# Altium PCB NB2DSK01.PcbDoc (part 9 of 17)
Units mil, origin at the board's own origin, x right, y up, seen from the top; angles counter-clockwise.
Board outline 11815 x 6500.03 mil, 8 copper layers (Top Layer, MidLayer1, MidLayer2, GND, PWR, MidLayer3, MidLayer4, Bottom Layer), stack 74.62 mil thick; 798 components, 1002 nets, 3927 pads, 3182 vias.
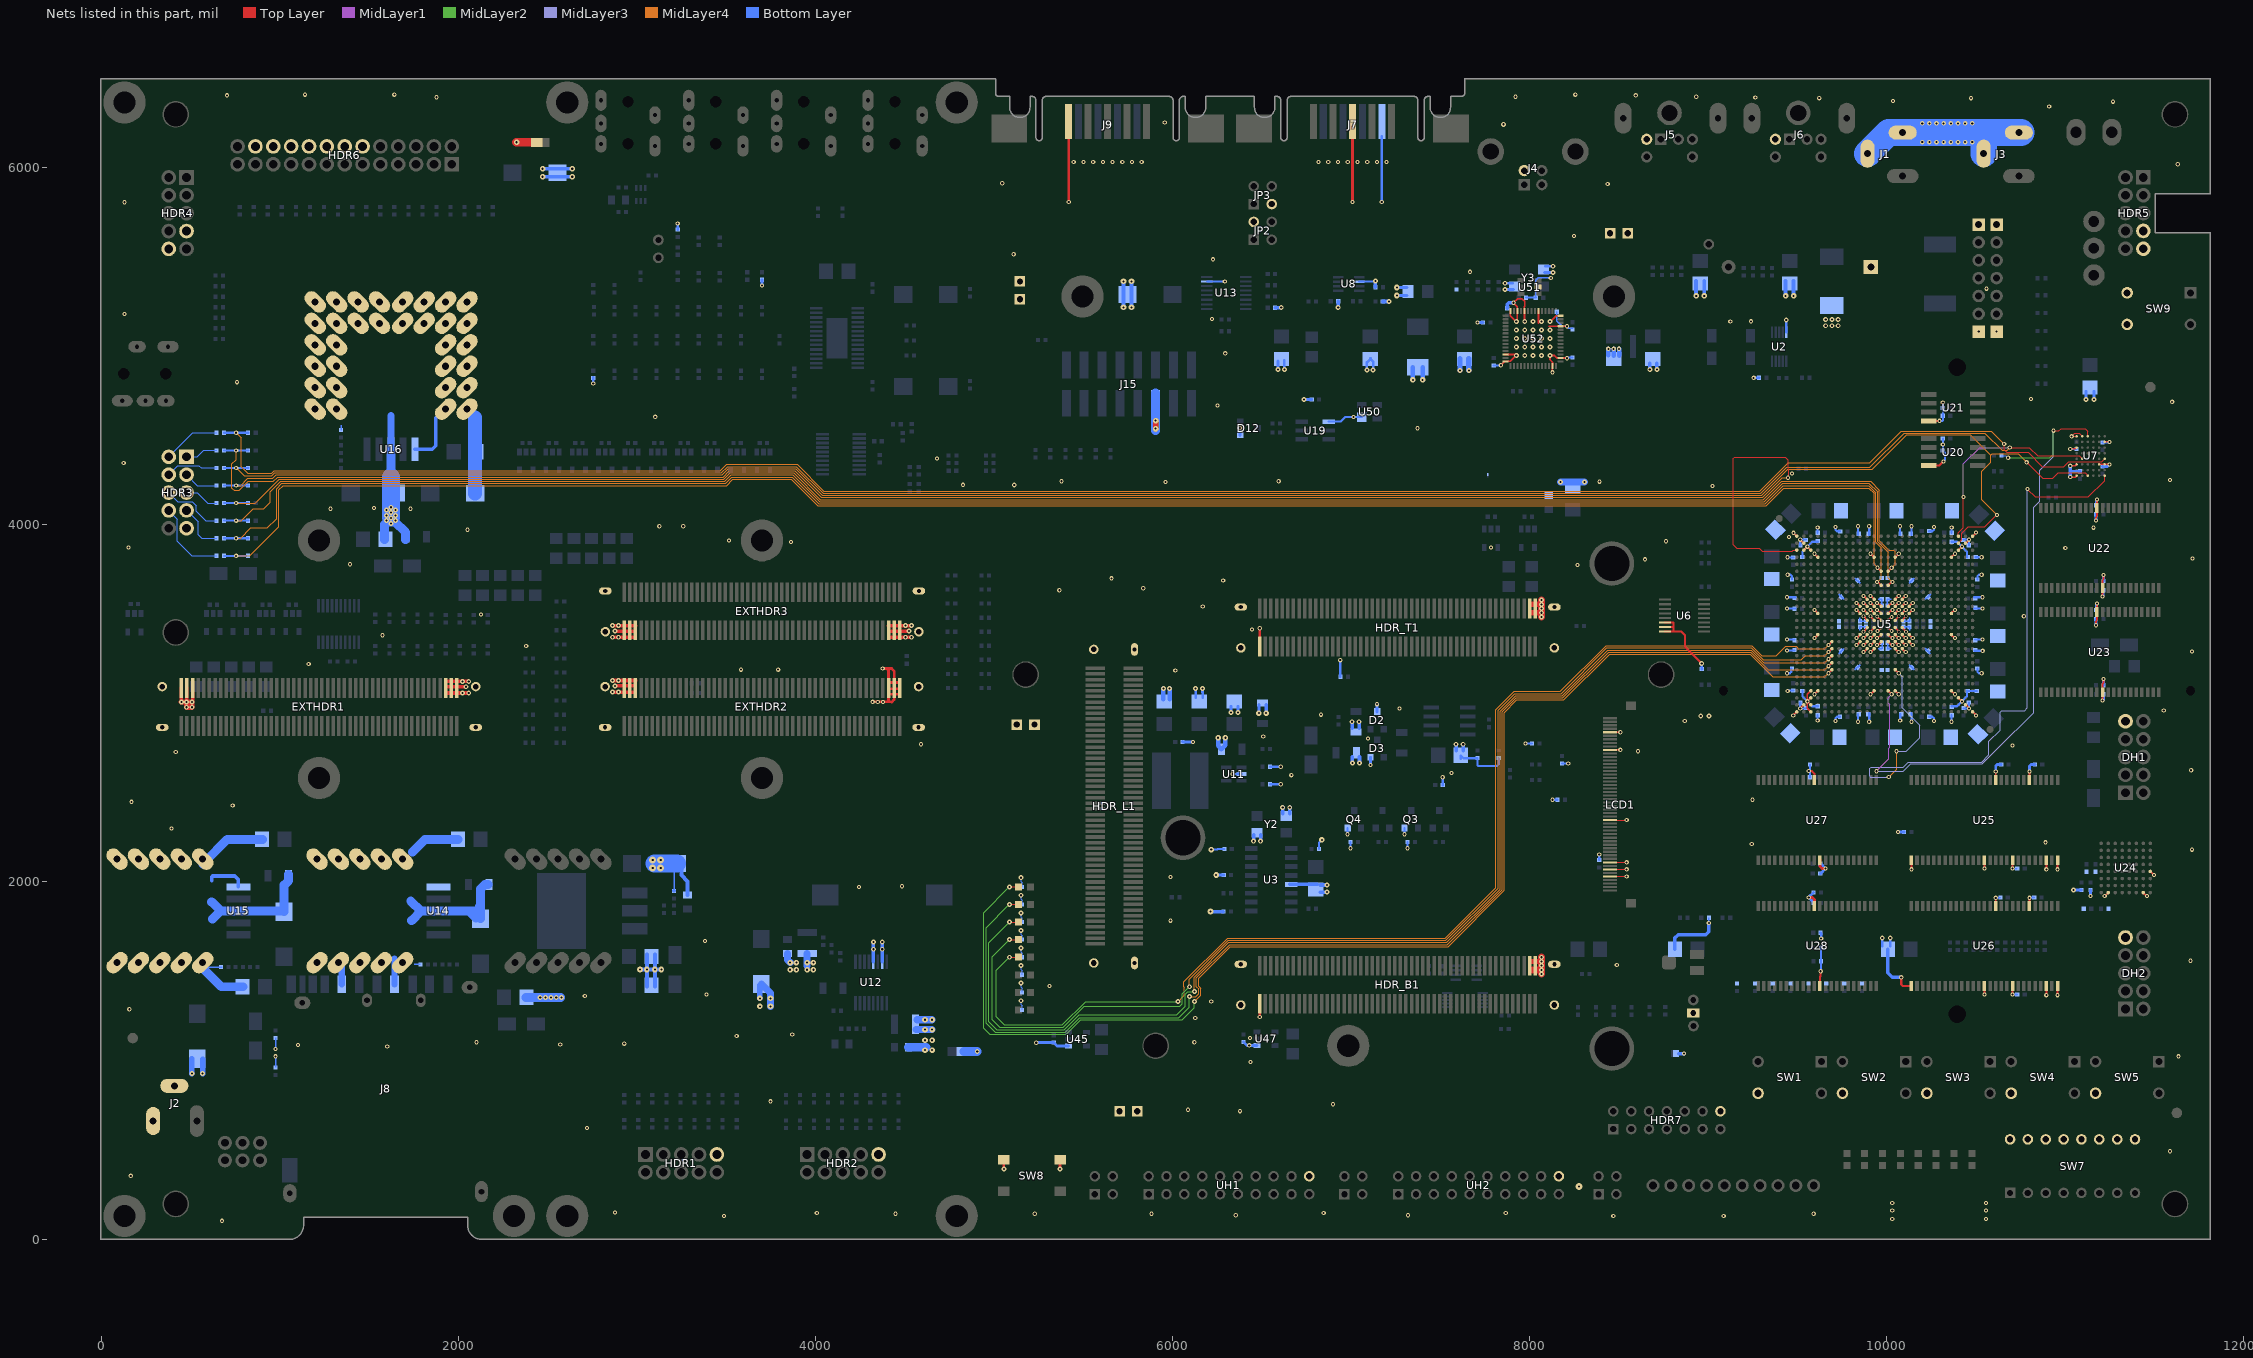
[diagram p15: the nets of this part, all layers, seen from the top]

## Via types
v1: diameter 23.62, hole 11.81, Top Layer to Bottom Layer, tented both sides, 1950 vias
v2: diameter 27.56, hole 11.81, Top Layer to Bottom Layer, tented both sides, 679 vias
v3: diameter 23.62, hole 11.81, Top Layer to Bottom Layer, 194 vias
v4: diameter 31.5, hole 11.81, Top Layer to Bottom Layer, tented both sides, 178 vias
v5: diameter 21.65, hole 11.81, Top Layer to Bottom Layer, tented both sides, 67 vias
v6: diameter 23.62, hole 11.81, Top Layer to Bottom Layer, tented bottom, 53 vias
v7: diameter 26, hole 11.81, Top Layer to Bottom Layer, tented both sides, 21 vias
v8: diameter 26, hole 11.81, Top Layer to Bottom Layer, 13 vias
v9: diameter 28, hole 11.81, Top Layer to Bottom Layer, 8 vias
v10: diameter 25.59, hole 11.81, Top Layer to Bottom Layer, tented both sides, 7 vias
v11: diameter 39.37, hole 11.81, Top Layer to Bottom Layer, tented both sides, 5 vias
v12: diameter 30, hole 11.81, Top Layer to Bottom Layer, 3 vias
v13: diameter 30, hole 11.81, Top Layer to Bottom Layer, tented both sides, 2 vias
v14: diameter 23, hole 11.81, Top Layer to Bottom Layer, tented both sides, 1 vias
v15: diameter 26.56, hole 11.81, Top Layer to Bottom Layer, tented both sides, 1 vias

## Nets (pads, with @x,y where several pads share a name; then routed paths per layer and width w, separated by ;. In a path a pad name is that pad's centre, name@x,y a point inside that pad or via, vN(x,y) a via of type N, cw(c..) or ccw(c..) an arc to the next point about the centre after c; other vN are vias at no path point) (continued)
GND: BT1.2 C1.2 C2.2 C3.2 C4.2 C10.2 C11.2 C12.2 C13.2 C14.2 C15.2 C18.2 C19.2 C20.2 C21.2 C22.2 C23.2 C24.2 C25.2 C26.2 C27.2 C28.2 C29.2 C30.2 C31.2 C32.2 C33.2 C34.2 C35.2 C36.2 C37.2 C38.2 C39.2 C40.2 C41.2 C42.2 C43.2 C44.2 C45.2 C46.2 C47.2 C48.2 C49.2 C50.2 C51.2 C52.2 C53.2 C54.2 C55.2 C56.2 C57.2 C58.2 C59.2 C60.2 C61.2 C62.2 C63.2 C64.2 C65.2 C66.2 C67.2 C68.2 C69.2 C70.2 C71.2 C72.2 C73.2 C74.2 C75.2 C76.2 C77.2 C78.2 C79.2 C80.2 C81.2 C82.2 C83.2 C84.2 C85.2 C86.2 C87.2 C88.2 C89.2 C90.2 C91.2 C92.2 C93.2 C94.2 C95.2 C96.2 C97.2 C98.2 C99.2 C100.2 C101.2 C102.2 C103.2 C104.2 C105.2 C106.2 C107.2 C108.2 C109.2 C110.2 C111.2 C112.2 C113.2 C114.2 C115.2 C116.2 C117.2 C118.2 C119.1 C120.2 C121.2 C122.2 C123.2 C124.2 C125.2 C126.2 C127.2 C128.2 C129.1 C130.2 C132.2 C133.2 C134.2 C135.2 C136.2 C137.2 C138.1 C139.1 C140.2 C141.2 C142.1 C143.2 C144.1 C146.1 C147.1 C148.1 C149.1 C150.2 C156.2 C157.2 C158.2 C159.2 C160.2 C161.2 C162.2 C163.2 C164.2 C165.2 C166.2 C167.2 C168.2 C169.2 C170.2 C172.2 C181.2 C189.2 C199.2 C200.1 C201.2 C202.1 C203.2 C204.2 C205.2 C206.2 C207.2 C208.2 C209.2 C210.2 C211.2 C212.2 C213.2 C214.2 C215.2 C216.2 C217.2 C218.2 C219.2 C220.2 C221.2 C222.2 C223.2 C224.2 C225.2 C226.2 C227.2 C228.2 C229.2 C230.2 C231.2 C232.2 C233.2 C234.2 C251.2 C253.2 C263.1 C264.1 C265.1 C266.2 C267.2 C268.2 C269.2 C270.2 C271.2 C272.1 C273.2 D1.1 D2.2 D3.2 D12.1 DH1.9 DH2.9 EXTHDR1.1 EXTHDR1.3 EXTHDR1.5 EXTHDR1.95 EXTHDR1.97 EXTHDR1.99 EXTHDR1.MH1 EXTHDR1.MH2 EXTHDR1.MH3 EXTHDR1.MH4 EXTHDR2.1 EXTHDR2.3 EXTHDR2.5 EXTHDR2.95 EXTHDR2.97 EXTHDR2.99 EXTHDR2.MH1 EXTHDR2.MH2 EXTHDR2.MH3 EXTHDR2.MH4 EXTHDR3.1 EXTHDR3.3 EXTHDR3.5 EXTHDR3.95 EXTHDR3.97 EXTHDR3.99 EXTHDR3.MH1 EXTHDR3.MH2 EXTHDR3.MH3 EXTHDR3.MH4 GP1.1 GP1.2 GP2.1 GP2.2 GP3.1 GP3.2 GP4.1 GP4.2 HDR1.9 HDR2.9 HDR3.9 HDR4.7 HDR4.10 HDR5.7 HDR5.9 HDR6.19 HDR6.20 HDR6.21 HDR6.22 HDR6.23 HDR6.24 HDR6.25 HDR7.14 HDR_B1.1 HDR_B1.98 HDR_B1.100 HDR_B1.MH1 HDR_B1.MH2 HDR_B1.MH3 HDR_B1.MH4 HDR_L1.MH1 HDR_L1.MH2 HDR_L1.MH3 HDR_L1.MH4 HDR_T1.1 HDR_T1.98 HDR_T1.100 HDR_T1.MH1 HDR_T1.MH2 HDR_T1.MH3 HDR_T1.MH4 J1.2 J1.3 J2.2 J2.3 J3.2 J3.3 J4.4 J5.3 J6.3 J7.3 J7.6 J8.3 J8.6 J9.5 J15.5 JP2.2 JP3.3 LCD1.5 LCD1.7 LCD1.9 LCD1.21 LCD1.41 LCD1.46 NT1.2 NT2.1 NT4.2 NT6.1 pad.0@88.68,1548.45 pad.0@88.68,2128.45 pad.0@208.68,1548.45 pad.0@208.68,2128.45 pad.0@328.68,1548.45 pad.0@328.68,2128.45 pad.0@448.68,1548.45 pad.0@448.68,2128.45 pad.0@568.68,1548.45 pad.0@568.68,2128.45 pad.0@1198.68,4648.45 pad.0@1198.68,4768.45 pad.0@1198.68,4888.45 pad.0@1198.68,5008.45 pad.0@1198.68,5128.45 pad.0@1198.68,5248.45 pad.0@1208.68,1548.45 pad.0@1208.68,2128.45 pad.0@1318.68,4648.45 pad.0@1318.68,4768.45 pad.0@1318.68,4888.45 pad.0@1318.68,5008.45 pad.0@1318.68,5128.45 pad.0@1318.68,5248.45 pad.0@1328.68,1548.45 pad.0@1328.68,2128.45 pad.0@1438.68,5128.45 pad.0@1438.68,5248.45 pad.0@1448.68,1548.45 pad.0@1448.68,2128.45 pad.0@1558.68,5128.45 pad.0@1558.68,5248.45 pad.0@1568.68,1548.45 pad.0@1568.68,2128.45 pad.0@1688.68,1548.45 pad.0@1688.68,2128.45 pad.0@1688.68,5128.45 pad.0@1688.68,5248.45 pad.0@1808.68,5128.45 pad.0@1808.68,5248.45 pad.0@1928.68,4648.45 pad.0@1928.68,4768.45 pad.0@1928.68,4888.45 pad.0@1928.68,5008.45 pad.0@1928.68,5128.45 pad.0@1928.68,5248.45 pad.0@2048.68,4648.45 pad.0@2048.68,4768.45 pad.0@2048.68,4888.45 pad.0@2048.68,5008.45 pad.0@2048.68,5128.45 pad.0@2048.68,5248.45 pad.0@8916.89,1266.02 pad.0@10514.96,5081.98 pad.0@10514.96,5681.95 pad.0@10614.96,5081.98 pad.0@10614.96,5681.95 Q3.2 Q4.2 R5.2 R19.2 R42.1 R44.1 R50.1 R51.1 R55.1 R58.1 R59.1 R62.2 R64.1 R65.1 R75.1 R78.2 R81.1 R82.1 R83.1 R92.1 R93.1 R94.1 R95.1 R96.1 R97.1 R98.1 R99.1 R100.1 R101.1 R102.1 R103.1 R104.1 R105.1 R106.1 R107.1 R312.2 R317.2 SW1.4 SW2.4 SW3.4 SW4.4 SW5.4 SW7.9 SW7.10 SW7.11 SW7.12 SW7.13 SW7.14 SW7.15 SW7.16 SW8.3 SW8.4 SW9.3 SW9.4 U2.5 U3.5 U5.A1 U5.A26 U5.AC3 U5.AC4 U5.AC12 U5.AC15 U5.AC23 U5.AD3 U5.AD24 U5.AE2 U5.AE3 U5.AE25 U5.AF1 U5.AF3 U5.AF26 U5.B2 U5.B25 U5.C2 U5.C3 U5.C24 U5.D4 U5.D12 U5.D15 U5.D23 U5.K11 U5.K12 U5.K15 U5.K16 U5.L10 U5.L11 U5.L12 U5.L13 U5.L14 U5.L15 U5.L16 U5.L17 U5.M4 U5.M10 U5.M11 U5.M12 U5.M13 U5.M14 U5.M15 U5.M16 U5.M17 U5.M23 U5.N11 U5.N12 U5.N13 U5.N14 U5.N15 U5.N16 U5.P11 U5.P12 U5.P13 U5.P14 U5.P15 U5.P16 U5.R4 U5.R10 U5.R11 U5.R12 U5.R13 U5.R14 U5.R15 U5.R16 U5.R17 U5.R23 U5.T10 U5.T11 U5.T12 U5.T13 U5.T14 U5.T15 U5.T16 U5.T17 U5.U11 U5.U12 U5.U15 U5.U16 U6.6 U6.7 U6.8 U7.A1 U7.A2 U7.B6 U7.C1 U7.F1 U7.F5 U7.F6 U7.H1 U8.2 U11.2 U12.13 U12.15 U13.15 U14.1 U14.3 U15.1 U15.3 U16.1 U16.3 U19.1 U20.4 U21.4 U22.12 U22.34 U23.12 U23.34 U24.E8 U24.H2 U24.H7 U25.6 U25.12 U25.28 U25.41 U25.46 U25.52 U25.54 U26.6 U26.12 U26.28 U26.41 U26.46 U26.52 U26.54 U27.12 U27.34 U28.12 U28.34 U45.1 U47.1 U50.1 U51.2 U52.6 U52.10 U52.12 U52.14 U52.26 U52.28 U52.41 U52.44 U52.53 U52.56 UH1.20 UH2.20 Y2.2 Y2.4 Y3.2 Y3.4 | length 31327.7
  Top Layer w5: LCD1.5@8448.82,2031.5 v1(8543.31,2031.5) ; LCD1.7@8448.82,2070.87 v1(8543.31,2070.87) ; LCD1.9@8448.82,2110.24 v1(8543.31,2110.24) ; LCD1.21@8448.82,2346.46 v1(8543.31,2346.46) ; U7.A1@11062.99,4496.06 v1(11035.43,4496.06) 11052.99,4513.62 11076.93,4513.62 U7.A2@11094.49,4496.06
  Top Layer w7.87: v1(7838.58,4893.7) v1(7838.58,4893.7) U52.28@7860.24,4915.35 ; U52.12@7931.1,5201.38 7931.1,5222.44 v1(7909.45,5244.09) 7933.07,5267.72 7956.69,5267.72 7972.44,5251.97 7972.44,5224.41 7970.47,5222.44 U52.10@7970.47,5197.78 U52.10@7970.47,5193.9 ; v1(8127.95,4854.33) U52.41@8127.95,4885.24 ; U52.53@8177.76,5112.2 v1(8208.68,5112.2) ; LCD1.41@8448.82,2740.16 v1(8507.87,2740.16) ; LCD1.46@8448.82,2838.58 v1(8507.87,2838.58) ; v1(9476.38,2933.07) U5.AF1@9496.06,2952.76 ; v1@9476.38,3956.7 v1(9477.68,3955.5) U5.A1@9496.06,3937.01 ; v1(9515.75,2972.44) U5.AE2@9535.43,2992.13 ; v1(9515.75,3917.32) U5.B2@9535.43,3897.64 ; U5.C2@9535.43,3858.27 v1(9555.12,3877.95) U5.C3@9574.8,3858.27 ; U5.AF3@9574.8,2952.76 9555.12,2972.44 v1(9555.12,3011.81) ; U5.AD3@9574.8,3031.5 v1(9555.12,3011.81) ; U5.AC3@9574.8,3070.87 9555.12,3051.18 v1(9555.12,3011.81) ; v1(9594.49,3051.18) U5.AC4@9614.17,3070.87 ; v1(9594.49,3366.14) U5.R4@9614.17,3385.83 ; v1(9594.49,3523.62) U5.M4@9614.17,3503.94 ; v1(9594.49,3838.58) U5.D4@9614.17,3818.9 ; v1(9830.71,3326.77) U5.T10@9850.39,3346.46 ; v1(9830.71,3366.14) U5.R10@9850.39,3385.83 ; v1(9830.71,3523.62) U5.M10@9850.39,3503.94 ; v1(9830.71,3562.99) U5.L10@9850.39,3543.31 ; v1(9870.08,3287.4) U5.U11@9889.76,3307.09 ; v1(9870.08,3326.77) U5.T11@9889.76,3346.46 ; v1(9870.08,3366.14) U5.R11@9889.76,3385.83 ; v5@9870.08,3402.76 U5.P11@9889.76,3425.2 ; v5@9870.08,3487.01 U5.N11@9889.76,3464.57 ; v1(9870.08,3523.62) U5.M11@9889.76,3503.94 ; v1(9870.08,3562.99) U5.L11@9889.76,3543.31 ; v1(9870.08,3602.36) U5.K11@9889.76,3582.68 ; v1(9909.45,3051.18) U5.AC12@9929.13,3070.87 ; v1(9909.45,3287.4) U5.U12@9929.13,3307.09 ; v1(9909.45,3326.77) U5.T12@9929.13,3346.46 ; v1(9909.45,3366.14) U5.R12@9929.13,3385.83 ; v5@9909.45,3403.15 U5.P12@9929.13,3425.2 ; v5@9909.45,3486.62 U5.N12@9929.13,3464.57 ; v1(9909.45,3523.62) U5.M12@9929.13,3503.94 ; v1(9909.45,3562.99) U5.L12@9929.13,3543.31 ; v1(9909.45,3602.36) U5.K12@9929.13,3582.68 ; v1(9909.45,3838.58) U5.D12@9929.13,3818.9 ; v5@9946.06,3562.99 U5.L13@9968.5,3543.31 ; v5@9946.46,3366.14 U5.R13@9968.5,3385.83 ; v5@9946.46,3523.62 U5.M13@9968.5,3503.94 ; v5(9946.85,3486.22) U5.N13@9968.5,3464.57 ; v5@9948.82,3326.77 U5.T13@9968.5,3346.46 ; v5(9948.82,3405.51) U5.P13@9968.5,3425.2 ; U5.T14@10007.87,3346.46 v5@10027.56,3326.77 ; U5.R14@10007.87,3385.83 v5@10029.92,3366.14 ; U5.P14@10007.87,3425.2 v5(10027.56,3405.51) ; U5.N14@10007.87,3464.57 v5(10027.56,3484.25) ; U5.M14@10007.87,3503.94 v5@10029.92,3523.62 ; U5.L14@10007.87,3543.31 v5@10030.32,3562.99 ; U5.AC15@10047.24,3070.87 v1(10066.93,3051.18) ; U5.U15@10047.24,3307.09 v1(10066.93,3287.4) ; U5.T15@10047.24,3346.46 v1(10066.93,3326.77) ; U5.R15@10047.24,3385.83 v1(10066.93,3366.14) ; U5.P15@10047.24,3425.2 v5@10066.93,3403.15 ; U5.N15@10047.24,3464.57 v5(10066.93,3488.19) ; U5.M15@10047.24,3503.94 v1(10066.93,3523.62) ; U5.L15@10047.24,3543.31 v1(10066.93,3562.99) ; U5.K15@10047.24,3582.68 v1(10066.93,3602.36) ; U5.D15@10047.24,3818.9 v1(10066.93,3838.58) ; U5.U16@10086.61,3307.09 v1(10106.3,3287.4) ; U5.T16@10086.61,3346.46 v1(10106.3,3326.77) ; U5.R16@10086.61,3385.83 v1(10106.3,3366.14) ; U5.P16@10086.61,3425.2 v5@10106.3,3405.51 ; U5.N16@10086.61,3464.57 v5@10106.3,3487.01 ; U5.M16@10086.61,3503.94 v1(10106.3,3523.62) ; U5.L16@10086.61,3543.31 v1(10106.3,3562.99) ; U5.K16@10086.61,3582.68 v1(10106.3,3602.36) ; U5.T17@10125.98,3346.46 v1(10145.67,3326.77) ; U5.R17@10125.98,3385.83 v1(10145.67,3366.14) ; U5.M17@10125.98,3503.94 v1(10145.67,3523.62) ; U5.L17@10125.98,3543.31 v1(10145.67,3562.99) ; U5.AC23@10362.2,3070.87 v1(10381.89,3051.18) ; U5.R23@10362.2,3385.83 v1(10381.89,3366.14) ; U5.M23@10362.2,3503.94 v1(10381.89,3523.62) ; U5.D23@10362.2,3818.9 v1(10381.89,3838.58) ; U5.AD24@10401.58,3031.5 v1(10421.26,3011.81) ; U5.C24@10401.58,3858.27 v1(10421.26,3877.95) ; U5.AE25@10440.95,2992.13 v1(10460.63,2972.44) ; U5.B25@10440.95,3897.64 v1(10460.63,3917.32) ; U5.AF26@10480.32,2952.76 v1(10500,2933.07) ; U5.A26@10480.32,3937.01 v1(10500,3956.7) ; v1(11027.56,4267.72) 11055.12,4267.72 U7.H1@11062.99,4275.59 ; v1(11027.56,4330.71) 11055.12,4330.71 U7.F1@11062.99,4338.58 ; v1(11027.56,4425.2) 11055.12,4425.2 U7.C1@11062.99,4433.07 ; U7.F5@11188.98,4338.58 U7.F6@11220.47,4338.58 v1(11248.03,4338.58) ; v1(11220.47,1921.08) U24.H2@11240.16,1940.77 ; U7.B6@11220.47,4464.57 v1(11248.03,4464.57) ; U24.H7@11437.01,1940.77 v1(11456.69,1921.08) ; U24.E8@11476.38,2058.88 v1(11496.06,2039.19)
  Top Layer w8: U52.28@7869.09,4915.35 7891.73,4915.35 v2@7925.2,4948.82 ; U52.14@7891.73,5193.9 7891.73,5171.26 7925.12,5137.87 v2@7925.2,5137.8 ; v2@8114.17,5137.8 8114.24,5137.87 8147.64,5171.26 U52.56@8170.28,5171.26
  Top Layer w9.84: U52.26@7861.61,4954.73 7865.35,4954.73 7925.19,4954.73 v2@7932.14,4954.73 ; v2@7931.1,5130.85 7931.1,5137.94 U52.12@7931.1,5197.78 U52.12@7931.1,5201.38 ; v2@7970.47,5130.85 7970.47,5137.94 U52.10@7970.47,5197.78 U52.10@7970.47,5201.38 ; 8049.21,5130.85 8049.21,5137.94 U52.6@8049.21,5197.78 U52.6@8049.21,5201.38 ; 8107.23,5112.21 8174.01,5112.21 U52.53@8177.76,5112.21 ; v1(10547.24,1370.08) U26.41@10547.25,1417.32 ; v1(10547.24,2074.8) U25.41@10547.25,2122.05 ; U26.12@10610.24,1866.14 v1(10610.24,1911.42) v1@10610.24,1915.36 ; U25.12@10610.24,2570.87 v1(10610.24,2618.11) ; v1(10704.72,1370.08) U26.46@10704.73,1417.32 ; v1(10704.72,2074.8) U25.46@10704.73,2122.05 ; U26.6@10799.21,1866.14 v1(10799.21,1911.42) v1@10799.21,1915.36 ; U25.6@10799.21,2570.87 v1(10799.21,2618.11) ; v1(11172.24,3437.99) 11172.24,3460.7 11177.17,3465.62 U23.34@11177.17,3511.81 v1(11177.17,3559.06) ; v1(11172.24,4024.61) 11172.24,4043.21 11177.17,4048.13 U22.34@11177.17,4094.49 v1(11177.17,4141.73) ; v1(11208.66,3015.75) U23.12@11208.66,3062.99 11208.66,3108.66 11213.58,3113.58 v1(11213.58,3136.81) ; v1(11208.66,3598.43) U22.12@11208.66,3645.67 11208.66,3690.2 11213.58,3695.13 v1(11213.58,3719.49)
  Top Layer w10: U52.41@8127.95,4892.72 8127.95,4910.69 8114.17,4924.47 8114.17,4948.82 8138.52,4948.82 8152.3,4935.04 U52.44@8170.28,4935.04 ; U52.44@8174.01,4935.19 v1@8206.95,4935.19
  Top Layer w11.81: v1(6488.19,1244.1) HDR_B1.1@6488.19,1318.9 ; HDR_T1.1@6488.19,3318.9 v1(6488.19,3421.26) ; v1(9562.99,2622.05) 9578.74,2622.05 9594.49,2606.3 U27.12@9594.49,2574.8 ; U28.34@9625.98,1417.32 9625.98,1467.98 9629.92,1471.92 v1(9629.92,1500.14) ; v1(10081,1466) 10081,1426 10089.68,1417.32 U26.28@10137.8,1417.32 ; v1(10137.8,2070.87) U25.28@10137.8,2122.05 ; U20.4@10234.25,4333.07 10295.07,4333.07 v1(10317,4355) ; U21.4@10234.25,4581.1 U21.4@10235.83,4582.68 ; v1(10893.7,1366.14) U26.52@10893.7,1417.32 ; v1(10893.7,2070.87) U25.52@10893.7,2122.05 ; v1(10956.69,1366.14) U26.54@10956.69,1417.32 ; v1(10956.69,2070.87) U25.54@10956.69,2122.05
  Top Layer w12: U6.8@8757.87,3401.93 8805.12,3401.93 ; U6.7@8757.87,3427.52 8803.15,3427.52 8805.12,3429.49 ; U6.6@8757.87,3453.11 8805.12,3453.11 8805.12,3429.49 ; v2(8963.58,3223.58) 8870.24,3316.93 8870.24,3381.69 8850,3401.93 8805.12,3401.93 ; v1(9555.12,3011.81) U5.AE3@9574.8,2992.13 ; U21.4@10235.83,4582.68 v1(10295.28,4582.68) ; 8805.12,3401.93 8805.12,3429.49
  Top Layer w15: v1(4320.6,3008.98) v1@4348.97,3008.98 ; v1(4349.37,3008.58) v1(4377.73,3008.58) 4403.34,3008.58 ; v1(4376.55,3195.34) 4399.15,3195.34 ; 4426.98,3008.58 4403.34,3008.58 ; 4427.77,3007.8 4440.95,3020.97 EXTHDR2.3@4440.95,3051.18 ; EXTHDR2.1@4472.44,3051.18 EXTHDR2.3@4440.95,3051.18 ; EXTHDR2.1@4472.44,3082.68 EXTHDR2.3@4440.95,3082.68 ; 4399.15,3195.34 4409.45,3185.04 4409.45,3118.11 EXTHDR2.5@4409.45,3086.61 EXTHDR2.5@4409.45,3082.68 ; 4399.15,3195.34 4426.71,3195.34 4440.95,3181.1 4440.95,3118.11 EXTHDR2.3@4440.95,3086.61 EXTHDR2.3@4440.95,3082.68 ; 4403.34,3008.58 4409.45,3014.69 EXTHDR2.5@4409.45,3051.18 ; EXTHDR2.5@4409.45,3051.18 EXTHDR2.5@4409.45,3082.68 ; EXTHDR2.5@4409.45,3051.18 EXTHDR2.3@4440.95,3051.18 ; EXTHDR2.5@4409.45,3082.68 EXTHDR2.3@4440.95,3082.68 ; EXTHDR2.3@4440.95,3051.18 EXTHDR2.3@4440.95,3082.68
  Top Layer w15.75: EXTHDR2.5@4409.45,3118.11 4440.95,3118.11 EXTHDR2.1@4472.44,3118.11 ; v2(5055.12,392.91) SW8.4@5055.12,444.49 SW8.4@5059.06,448.43 ; v2(5370.47,392.91) SW8.3@5370.47,444.49 ; J9.5@5418.28,6258.86 v1(5418.57,5807.92) ; v1(7007.89,5808.9) J7.3@7008,6259.84 ; v1(9562.99,1913.39) 9582.68,1913.39 9594.49,1901.58 U28.12@9594.49,1866.14 ; U27.34@9625.98,2122.05 9625.98,2086.62 9637.8,2074.8 v1(9657.48,2074.8)
  Top Layer w19.68: v2@448.82,3008.58 EXTHDR1.99@448.82,3086.61 ; v2@480.32,3010.08 EXTHDR1.97@480.31,3086.61 ; v2@511.81,3011.57 EXTHDR1.95@511.81,3086.61 ; EXTHDR1.5@1929.13,3123.45 1960.63,3123.45 1992.13,3123.45 v2(2023.68,3123.45) v2(2058.68,3123.45) ; EXTHDR1.5@1929.74,3058.45 1960.63,3058.45 1992.13,3058.45 v2(2023.68,3058.45) v2(2058.68,3058.45) ; EXTHDR1.5@1930.17,3093.45 1960.63,3093.45 1992.13,3093.45 v2(2043.68,3093.45) ; v2(2862.95,3063.43) v2(2897.95,3063.43) 2929.13,3063.43 2960.63,3063.43 EXTHDR2.95@2991.9,3063.43 ; v2(2862.95,3128.43) v2(2897.95,3128.43) 2929.13,3128.43 2960.63,3128.43 2992.13,3128.43 EXTHDR2.95@2992.5,3128.43 ; v2(2862.95,3370.51) v2(2897.95,3370.51) 2929.13,3370.51 2960.63,3370.51 EXTHDR3.5@2991.9,3370.51 ; v2(2862.95,3435.51) v2(2897.95,3435.51) 2929.13,3435.51 2960.63,3435.51 2992.13,3435.51 EXTHDR3.5@2992.5,3435.51 ; v2(2877.95,3098.43) 2929.13,3098.43 2960.63,3098.43 EXTHDR2.95@2991.47,3098.43 ; v2(2877.95,3405.51) 2929.13,3405.51 2960.63,3405.51 EXTHDR3.5@2991.47,3405.51 ; EXTHDR3.95@4409.07,3435.51 4409.45,3435.51 4440.95,3435.51 4472.44,3435.51 v2(4503.62,3435.51) v2(4538.62,3435.51) ; EXTHDR3.95@4409.68,3370.51 4440.95,3370.51 4472.44,3370.51 v2(4503.62,3370.51) v2(4538.62,3370.51) ; EXTHDR3.95@4410.11,3405.51 4440.95,3405.51 4472.44,3405.51 v2(4523.62,3405.51)
  Top Layer w29.53: HDR_B1.98@8007.87,1555.12 8031.5,1555.12 v2(8066.93,1555.12) ; HDR_T1.98@8007.87,3555.12 8031.5,3555.12 v2(8066.93,3555.12) ; 8011.81,3507.87 8031.5,3507.87 v2(8066.93,3507.87)
  Top Layer w30: v2(448.68,3008.45) v2(478.68,3008.45) ; v4(5905.51,4538.77) v4(5905.51,4583.68) ; v2(478.68,3008.45) v2(478.68,2978.45) v2(508.68,2978.45) v2(508.68,3008.45) v2(478.68,3008.45)
  Top Layer w39.37: 8011.81,1507.87 8031.5,1507.87 v2(8066.93,1507.87) ; v2(8066.93,1484.25) v2(8066.93,1507.87) ; v2(8066.93,1578.74) v2(8066.93,1555.12) v2(8066.93,1531.5) v2(8066.93,1507.87) ; v2(8066.93,3484.25) v2(8066.93,3507.87) v2(8066.93,3531.5) v2(8066.93,3555.12) v2(8066.93,3578.74)
  Top Layer w50: v4@2324.81,6142.82 v4(2326.58,6142.82) NT4.2@2409.4,6142.8
  MidLayer1 w30: v4(5905.51,4538.77) v4(5905.51,4583.68)
  MidLayer2 w30: v4(5905.51,4538.77) v4(5905.51,4583.68)
  MidLayer4 w30: v4(5905.51,4538.77) v4(5905.51,4583.68)
  MidLayer3 w30: v4(5905.51,4538.77) v4(5905.51,4583.68)
  Bottom Layer w5: HDR4.7@477.95,5644.88 HDR4.7@477.95,5645.67 ; v2(5151.97,1335.04) 5151.97,1311.76 5157.17,1306.56 R99.1@5157.17,1283.47 ; v2(5151.97,1433.47) 5151.97,1410.18 5157.17,1404.98 R98.1@5157.17,1381.89 ; v2(5151.97,1531.89) 5151.97,1508.61 5157.17,1503.41 R97.1@5157.17,1480.32 ; v2(5151.97,1630.32) 5151.97,1607.03 5157.17,1601.83 R96.1@5157.17,1578.74 ; v2(5151.97,1728.74) 5151.97,1705.46 5157.17,1700.26 R95.1@5157.17,1677.17 ; v2(5151.97,1827.17) 5151.97,1803.88 5157.17,1798.68 R94.1@5157.17,1775.59 ; v2(5151.97,1925.59) 5151.97,1902.31 5157.17,1897.11 R93.1@5157.17,1874.02 ; v2(5151.97,2024.02) 5151.97,2000.73 5157.17,1995.53 R92.1@5157.17,1972.44
  Bottom Layer w7.87: C269.2@8034.45,5272.46 8034.45,5370.49 8047.05,5383.09 v1(8118.5,5383.09) ; v1(9003.45,1770.36) R42.1@9003.45,1799.21 ; v1@9547.25,3877.95 v1(9555.12,3877.95) v1@9555.12,3885.83 ; 9732.28,3279.53 9745.23,3292.47 C32.2@9745.23,3294.14 9746.9,3294.14 9759.84,3307.09 ; 9732.28,3610.24 9745.23,3597.29 C29.2@9745.23,3595.62 9746.9,3595.62 9759.84,3582.68 ; C52.2@9736.22,2925.2 9738.46,2925.2 9740.16,2925.2 C52.2@9739.61,2924.65 ; 9821.96,3188.11 9835.78,3201.92 C27.2@9837.45,3201.92 9837.45,3203.59 9851.26,3217.4 ; 9822.83,3700.79 9835.78,3687.84 C31.2@9837.45,3687.84 9837.45,3686.17 9850.39,3673.23 ; 9849.41,3410.43 C85.2@9849.41,3429.14 ; C85.2@9849.41,3429.14 C107.2@9883.2,3429.45 ; 9849.41,3479.33 C105.2@9849.41,3460.63 C64.2@9883.2,3460.45 ; 9951.28,3306.1 C100.2@9972.44,3306.1 ; 9951.28,3583.66 C86.2@9972.44,3583.66 C92.2@9972.68,3548.93 ; C100.2@9971.46,3308.07 C100.2@9971.95,3307.58 ; C100.2@9973.44,3305.24 9973.45,3306.1 C62.2@9973.68,3339.97 ; C93.2@10003.68,3548.93 C94.2@10003.68,3583.42 ; C104.2@10003.94,3306.1 C104.2@10004.68,3306.1 ; C94.2@10003.94,3582.68 C94.2@10004.92,3581.69 ; C94.2@10003.94,3583.66 10025.1,3583.66 ; C104.2@10004.68,3305.49 C104.2@10004.68,3306.1 ; C110.2@10004.68,3339.97 C104.2@10004.68,3306.1 ; 10025.1,3306.1 C104.2@10004.68,3306.1 ; C63.2@10093.16,3429.45 C95.2@10127.95,3429.13 10127.95,3419.29 10127.95,3411.42 10125.98,3409.45 ; C96.2@10093.16,3460.45 C91.2@10127.95,3460.63 10127.95,3470.47 10127.95,3478.35 10125.98,3480.32 ; 10125.12,3217.4 10138.93,3203.59 C30.2@10138.93,3201.92 10140.6,3201.92 10153.54,3188.98 ; C95.2@10125.49,3428.64 C95.2@10125.98,3429.13 ; 10125.98,3673.23 10138.93,3686.17 C33.2@10138.93,3687.84 10140.6,3687.84 10153.54,3700.79 ; 10215.66,3307.96 10230.31,3293.31 C26.2@10231.15,3292.47 ; 10216.54,3582.68 10229.48,3595.62 C28.2@10231.15,3595.62 10231.15,3597.29 10246.6,3612.75 ; C26.2@10231.15,3294.14 C26.2@10231.15,3292.47 ; C26.2@10235.63,3299.21 C26.2@10236.22,3299.21 ; 10244.09,3279.53 C26.2@10231.15,3292.47
  Bottom Layer w8: pad.0@573.68,1523.45 R78.2@670.92,1523.45 R78.2@677.5,1523.45 ; R83.1@976.38,962.13 v1(976.38,1023.62) ; v1(976.38,1064.96) R82.1@976.38,1126.46 ; R81.1@1343.68,4531.03 1343.68,4558.45 ; 1753.68,1538.45 R75.1@1787.5,1538.45 ; R62.2@3208.68,1950.83 C137.2@3208.68,2098.45
  Bottom Layer w9.84: C272.1@8152.02,5193.1 8152.02,5141.98 8181.8,5112.2 v1(8208.68,5112.2) 8219.51,5101.38 C265.1@8240.16,5101.38 ; v1(10610.24,1911.42) C221.2@10635.82,1911.42 ; v1(10704.72,1370.08) C222.2@10731.3,1370.08 ; v1(10704.72,2074.8) C220.2@10728.35,2074.8 ; v1@10799.21,1913.39 C225.2@10825.79,1913.39
  Bottom Layer w10: v1(8208.68,4933.45) 8213.22,4937.99 C264.1@8240.16,4937.99
  Bottom Layer w11.81: v4@6220.47,2185.04 v4(6216.54,2181.1) 6248.84,2181.1 6252.78,2185.04 C13.2@6290.36,2185.04 ; v1(6336.61,2604.33) U11.2@6385.83,2604.33 ; C12.2@6819.88,2185.04 6819.88,2219.49 v4(6836.62,2236.22) ; v1(6980.64,2267.47) Q4.2@6980.64,2302.43 ; v1(6996.86,2188.73) R51.1@6996.86,2223.69 ; v1(7013,4604) U50.1@7060.24,4604 ; v1(7299.53,2267.47) Q3.2@7299.53,2302.43 ; v1(7315.75,2188.73) R50.1@7315.75,2223.69 ; C268.2@7799.21,4892.72 7837.6,4892.72 v1(7838.58,4893.7) ; v1(7977.32,2775.59) R44.1@8012.28,2775.59 ; v1(8127.95,2460.63) C118.2@8156.5,2460.63 ; C115.2@8181.1,2662.97 v1(8216.06,2662.97) ; C129.1@8389.76,2123.03 v1(8389.76,2153.54) ; C232.2@9569.88,2586.61 9569.88,2615.16 v1(9562.99,2622.05) 9569.88,2628.94 C228.2@9569.88,2657.48 ; v1@9630.91,1499.16 v1(9629.92,1500.14) 9630.91,1501.13 C229.2@9630.91,1556.18 C233.2@9630.91,1631.93 ; v1(10075,2905) 10075.39,2905.39 10075.39,2939.78 C71.2@10075.39,2939.96 ; v1(10295.28,4582.68) 10311.68,4582.68 10316,4587 10316,4609.41 C200.1@10313.96,4611.45 C201.2@10313.98,4654.74 v1(10313.98,4685.04) ; C202.1@10313.98,4484.25 v1(10313.98,4449.8) C199.2@10313.98,4417.32 10313.98,4417.16 10327,4404.14 10327,4365 v1(10317,4355) ; 11027.56,4299.21 11028.54,4300.2 ; v1(11027.56,4425.2) 11028.54,4424.21 C119.1@11062.99,4424.21 ; C208.2@11172.24,3523.62 11172.24,3554.13 v1(11177.17,3559.06) ; C207.2@11172.24,4110.24 11172.24,4132.87 11177.17,4137.8 v1(11177.17,4141.73) ; v1(11208.66,3598.43) 11213.58,3603.35 C204.2@11213.58,3633.86 ; C122.2@11208.66,4461.61 11245.08,4461.61 v1(11248.03,4464.57) ; v1@11246.06,4338.58 v1(11248.03,4338.58)
  Bottom Layer w12: U13.15@6192.59,5363.19 v1(6292.81,5363.19) ; U19.1@6874.27,4578.53 6942.53,4578.53 6968,4604 v1(7013,4604) ; R19.2@6939.43,3149.6 v1(6939.43,3242.47) ; U8.2@7045.11,5362.28 7133.41,5362.28 v2(7136.28,5365.15) ; C133.2@7614.06,2689.57 C133.2@7614.06,2708.66 7629.33,2693.39 R58.1@7708.54,2693.39 7708.54,2651.62 ; 7710.09,2650.08 7817.08,2650.08 7826.65,2659.65 R59.1@7826.65,2693.39 ; C270.2@7980.28,5272.46 C269.2@8034.45,5272.46 ; U2.5@9437.03,5078.18 v2(9437.03,5146.8) ; v1(9440.95,3169.29) 9456.65,3169.29 9465.16,3177.8 C40.2@9465.16,3195.16 ; v1(9440.95,3295.87) 9483.01,3295.87 C113.2@9483.27,3295.87 ; v1(9440.95,3357.68) 9483.01,3357.68 C72.2@9483.27,3357.68 ; v1(9440.95,3531.5) 9483.27,3531.5 C77.2@9488.19,3531.5 ; v1(9440.95,3594.49) 9483.27,3594.49 C109.2@9488.19,3594.49 ; v1(9444.88,3720.47) 9460.59,3720.47 9469.09,3711.97 C44.2@9469.09,3694.61 ; v1@9447.73,3071.69 C75.2@9476.76,3071.69 ; v1@9447.72,3818.08 C106.2@9476.76,3818.08 ; C47.2@9515.75,3003.94 9515.75,3003.35 v1(9515.75,2972.44) C50.2@9547.24,2972.44 ; C53.2@9515.75,3885.83 v1(9515.75,3917.32) 9546.65,3917.32 C45.2@9547.24,3917.32 ; C98.2@9527.56,3070.87 9527.56,3069.17 9527.56,3039.37 v1(9555.12,3011.81) 9582.68,2984.25 9612.87,2984.25 C81.2@9614.17,2984.25 ; C80.2@9527.56,3818.9 9527.56,3820.2 9527.56,3850.4 v1(9555.12,3877.95) 9582.68,3905.51 9613.01,3905.51 C78.2@9614.17,3905.51 ; v1(9613.03,2904.41) C99.2@9613.03,2933.45 ; C89.2@9613.03,3956.31 v1(9613.03,3985.35) ; v1(9712.6,2901.58) 9712.6,2917.28 9721.11,2925.79 C52.2@9738.46,2925.79 ; v1(9712.6,3988.19) 9712.6,3972.48 9721.11,3963.98 C41.2@9738.46,3963.98 ; v1(9838.58,2897.64) 9838.58,2939.78 C97.2@9838.58,2939.96 ; C112.2@9838.58,3944.88 9838.63,3950.16 v1(9838.98,3992.52) ; v1(9901.57,2897.64) 9901.58,2939.78 C76.2@9901.58,2944.88 ; C84.2@9901.58,3944.88 9901.58,3950.12 v1(9901.57,3992.13) ; C83.2@10074.8,3944.88 10074.8,3950.12 v1(10074.8,3992.13) ; v1(10137.8,2897.64) 10137.8,2939.78 C103.2@10137.8,2944.88 ; C111.2@10137.8,3944.88 10137.8,3950.12 v1(10137.8,3992.13) ; C42.2@10237.91,2925.79 10255.27,2925.79 10263.78,2917.28 v1(10263.78,2901.58) ; C38.2@10237.91,3963.98 10255.27,3963.98 10263.78,3972.48 v1(10263.78,3988.19) ; v1(10362.2,2897.64) C88.2@10362.21,2933.45 ; C70.2@10362.21,2984.25 10363.35,2984.25 10393.7,2984.25 v1(10421.26,3011.81) 10448.82,3039.37 10448.82,3069.78 C69.2@10448.82,3070.87 ; C79.2@10362.21,3905.51 10363.5,3905.51 10393.7,3905.51 v1(10421.26,3877.95) 10448.82,3850.4 10448.82,3820.12 C73.2@10448.82,3818.9 ; C87.2@10363.35,3956.31 v1(10363.35,3985.35) ; C43.2@10429.13,2972.44 10429.73,2972.44 v1(10460.63,2972.44) C48.2@10460.63,3003.94 ; C46.2@10429.13,3917.32 v1(10460.63,3917.32) 10460.63,3886.42 C49.2@10460.63,3885.83 ; C69.2@10453.78,3069.88 C108.2@10503.94,3069.88 ; C82.2@10488.19,3531.5 10496.35,3531.5 v1(10535.43,3531.5) ; C90.2@10488.19,3594.49 10495.35,3594.49 v1(10535.43,3594.49) ; C102.2@10493.11,3294.69 10495.35,3294.69 v1(10537.21,3294.69) ; C74.2@10493.68,3358.27 10495.35,3358.27 v1(10535.43,3358.27) ; C101.2@10498.68,3818.9 v1(10531.5,3818.9) ; C51.2@10507.28,3195.16 10507.28,3177.8 10515.79,3169.29 v1(10531.5,3169.29) ; C39.2@10507.28,3694.61 10507.28,3711.97 10515.79,3720.47 v1(10531.5,3720.47)
  Bottom Layer w15: C181.2@3228.68,5654.12 v1(3228.68,5688.45)
  Bottom Layer w15.75: v1(2755.91,4791.34) C172.2@2755.91,4821.85 C172.2@2755.91,4825.79 ; v1(3700.79,5341.34) C189.2@3700.79,5373.03 ; v1@5237.78,1100.78 C251.2@5334.73,1100.78 5353.43,1082.08 U45.1@5417.41,1082.08 ; C141.2@6055.12,2787.4 6057.58,2784.94 6059.06,2783.47 v1(6114.17,2783.47) ; C143.2@6129.92,3031.5 v2@6129.92,3083.45 ; v2(6168.68,3083.45) C143.2@6169.29,3031.5 ; v4(6244.09,2039.37) C14.2@6286.42,2039.37 ; v2(6326.77,2948.82) C132.2@6326.77,2984.25 ; v2(6366.14,2948.82) C132.2@6366.14,2984.25 ; D12.1@6378.66,4500.22 D12.1@6378.61,4504.6 v2(6378.66,4542.55) ; C253.2@6398.2,1103.8 6416.9,1085.1 v1(6429.69,1085.1) U47.1@6473,1085.1 ; R64.1@6546.77,2547.24 v1(6606.3,2547.24) ; R65.1@6546.77,2645.67 v1(6606.3,2645.67) ; v2(6590.61,4870.69) C123.2@6590.61,4917.94 ; v2(6626.05,4870.69) C123.2@6626.05,4921.87 ; v2@6733.08,4702 v2(6737.02,4702) C125.2@6779.34,4702 ; v2(7088.14,4866.76) 7088.14,4910.07 C124.2@7107.83,4929.75 ; C124.2@7107.83,4933.69 C124.2@7107.83,4929.75 ; v1(7108.27,2655.51) D3.2@7108.27,2698.82 ; v2(7123.57,4866.76) 7123.57,4914 C124.2@7107.83,4929.75 ; D2.2@7145.67,2952.76 D2.2@7145.67,2954.73 v1(7145.67,2996.06) ; J7.6@7171.46,6174.79 v1(7171.47,5808.9) ; C134.2@7512.8,2543.31 v1(7512.8,2586.61) ; v1(7708.66,5133.86) C267.2@7739.17,5133.86 ; v2(7861.93,5317.9) Y3.2@7909.17,5317.9 ; v2(7861.93,5353.34) Y3.2@7905.23,5353.34 ; Y3.4@8082.96,5412.9 v2(8130.2,5412.9) ; Y3.4@8086.89,5448.34 v2(8130.2,5448.34) ; C117.2@8963.58,3192.91 C117.2@8963.58,3194.31 ; v2(8963.58,3223.58) C117.2@8963.58,3194.31 ; C117.2@8964.96,3192.91 8965.35,3193.31 8964.18,3193.97 C117.2@8963.58,3194.31 ; v1(9254.55,4823.54) C11.2@9285.06,4823.54 ; C234.2@9589.57,1881.89 9589.57,1886.81 v1(9562.99,1913.39) 9562.99,1914.37 C230.2@9589.57,1940.95 ; C231.2@9626.97,2047.24 9629.92,2047.24 v1(9657.48,2074.8) 9629.92,2102.36 C227.2@9626.97,2102.36 ; C226.2@9629.62,1715.33 9632.57,1712.38 v1(9632.57,1683.84) ; C218.2@9974.58,1641.83 v2(9974.58,1686.83) ; C218.2@10019.58,1641.83 v2(10019.58,1686.83) ; v1(10063.1,2280.7) 10096.55,2280.7 C224.2@10097.55,2280.7 ; v1(10610.24,2618.11) 10610.24,2649.47 10618.25,2657.48 C219.2@10640.75,2657.48 ; v1(10799.21,2618.11) 10799.21,2649.47 10807.23,2657.48 C223.2@10829.72,2657.48 ; 11028.54,4300.2 C121.2@11082.68,4300.2 ; v2(11044.88,1955.53) C212.2@11090.55,1955.53 ; v2(11116,4703) C217.2@11116,4748 ; v1(11141.73,1921.08) C215.2@11141.73,1955.53 ; v2(11161,4703) C217.2@11161,4748 ; v1(11172.24,3437.99) C205.2@11172.24,3472.44 ; v1(11172.24,4024.61) C203.2@11172.24,4059.06 ; v1(11208.66,3015.75) 11213.58,3020.67 C206.2@11213.58,3051.18 ; C120.2@11208.66,4327.76 11235.24,4327.76 v1@11246.06,4338.58 ; C210.2@11213.58,3102.36 v1(11213.58,3136.81) ; C209.2@11213.58,3685.04 v1(11213.58,3719.49)
  Bottom Layer w17: v4(7256.38,5284.64) R317.2@7313.35,5284.64 ; v4(7256.38,5329.55) R317.2@7313.35,5329.55
  Bottom Layer w18: U12.15@4374.08,1553.55 v2(4374.08,1623.45) v2(4374.08,1663.05) ; v4(6483.45,2945.52) C139.1@6483.45,2994.77 ; v4(6524.43,2945.52) C139.1@6524.43,2994.77
  Bottom Layer w19.68: v4(6212.6,1834.65) R5.2@6282.91,1834.65 ; v2(6453.91,2228.46) Y2.2@6453.91,2263.89 ; v2(6493.28,2228.46) Y2.2@6493.28,2263.89 ; Y2.4@6616.95,2381.78 v2(6616.95,2417.21) ; U3.5@6655.51,1987.01 U3.5@6665.35,1987.01 6801.5,1987.01 C15.2@6810.24,1987.01 ; Y2.4@6656.32,2381.78 v2(6656.32,2417.21) ; C15.2@6828.7,1943.79 v2(6864.13,1943.79) ; C15.2@6828.7,1983.16 v2(6864.13,1983.16) ; 7005.92,2861.84 v2(7005.92,2897.28) ; v2(7007.72,2666.21) 7007.72,2701.64 ; 7045.29,2861.84 v2(7045.3,2897.28) ; v2(7047.09,2666.21) C130.2@7047.09,2701.64 ; C133.2@7588.48,2735.87 v2(7588.48,2771.3) ; C133.2@7627.85,2735.87 v2(7627.85,2771.3) ; v2(8672.83,4871.05) C10.2@8672.83,4906.48 ; v2(8712.2,4871.05) C10.2@8712.2,4906.48 ; v1(11027.56,4267.72) 11027.56,4299.21 v1@11027.56,4326.77
  Bottom Layer w20: 618.68,2008.45 618.68,2028.45 623.68,2033.45 748.68,2033.45 768.68,2013.45 U15.1@768.68,1972.31 ; U16.1@1757.54,4423.45 1853.68,4423.45 1873.68,4443.45 1873.68,4598.45 ; U12.13@4324.18,1553.45 v2(4324.18,1623.45) v2(4324.18,1662.95) ; C156.2@6574.48,5216.54 v2(6608.93,5216.54) ; v2(6927.83,5217.61) C127.2@6927.83,5252.06 ; R55.1@7136.28,5330.7 v2(7136.28,5365.15) ; C126.2@7177.41,5251.06 v2(7211.86,5251.06) ; C263.1@7874,5213.57 7874,5236 7882.09,5244.09 v1(7909.45,5244.09) ; C114.2@8813.31,1623 8813.31,1686.31 8832,1705 8987,1705 9003.45,1721.45 v1(9003.45,1770.36) ; 8836,1039 v1(8865,1039) ; C218.2@10005.89,1623 10005.89,1491.11 10031,1466 v1(10081,1466)
  Bottom Layer w22: v4(2471.99,5949.69) 2555.04,5949.69 v4(2638.13,5949.69) ; v4(2471.99,5994.61) 2555.04,5994.61 v4(2638.13,5994.61) ; v4(3017.28,1509.85) v4(3056.28,1509.85) ; C136.2@3056.28,1414.95 3056.28,1421.26 v4(3056.28,1509.85) ; C135.2@3056.28,1592.92 3056.28,1582.68 v4(3056.28,1509.85) ; C136.2@3101.2,1414.95 3101.2,1421.26 v4(3101.2,1509.85) ; C135.2@3101.2,1592.92 3101.2,1582.68 v4(3101.2,1509.85) ; v4(3137.28,1509.85) v4(3101.2,1509.85) ; C137.2@3224.6,2103.16 3249,2078.77 3249,2038 3283.56,2003.44 C138.1@3283.56,1927.18 ; v4(5725.12,5218) 5725.12,5290.81 v4(5725.12,5363.65) ; v4(5770.03,5218) 5770.03,5290.81 v4(5770.03,5363.65) ; v4(8932.79,5282.33) 8932.79,5351.22 C169.2@8932.79,5365.4 ; v4(8977.7,5282.33) 8977.7,5351.22 C169.2@8977.7,5365.4 ; v4(9433.72,5282.33) 9433.72,5351.22 C170.2@9433.72,5365.4 ; v4(9478.64,5282.33) 9478.64,5351.22 C170.2@9478.64,5365.4 ; v4(3056.28,1509.85) v4(3101.2,1509.85)
  Bottom Layer w23.62: v4(7345.88,4812) C271.2@7345.88,4882.87 ; v4(7401,4812) C271.2@7401,4882.87
  Bottom Layer w25: C116.2@5948.68,3023.45 v2(5948.68,3083.45) ; C116.2@5983.68,3023.45 v2(5983.68,3083.45) ; v4(6255.1,2808.03) 6255.1,2762.62 C144.1@6273.62,2744.1 6296.08,2766.55 v4(6296.08,2808.03) ; C273.2@8440.68,4951.08 v1(8440.68,4986.08) ; C273.2@8470.68,4946.08 v1(8470.68,4986.08) ; C273.2@8500.68,4946.08 v1(8500.68,4986.08)
  Bottom Layer w30: v2(507.93,926.74) 507.93,1010.84 C2.2@507.93,1011.74 ; v2(567.93,926.74) C2.2@567.93,1006.74 ; v4(3688.68,1348.45) C150.2@3688.68,1423.45 ; v2(7609.76,4864.63) C266.2@7609.76,4929.63 ; v2(7659.76,4864.63) C266.2@7659.76,4929.63
  Bottom Layer w35: J8.6@1347.22,1427.67 pad.0@1347.22,1547 ; J8.3@1642.5,1427.67 1642.5,1548.45 1642.5,1569.63
  Bottom Layer w39.37: C150.2@3696.85,1429.13 3748.68,1377.3 v4(3748.68,1348.45) v4(3748.68,1303.45) ; v2(8173.23,4240.16) 8240.16,4240.16 v2(8307.09,4240.16)
  Bottom Layer w40: U16.3@1623.68,4423.45 1623.68,4613.45 ; C148.1@3843.68,1599.08 3843.68,1563.45 v4(3858.68,1548.45) ; 3953.68,1529.8 v4(3953.68,1548.45) C149.1@3953.68,1599.4 ; C147.1@4563.68,1173.45 v4(4613.68,1173.45) v4(4653.68,1173.45) ; C147.1@4568.68,1228.45 v4(4613.68,1228.45) v4(4653.68,1228.45)
  Bottom Layer w50: pad.0@569.21,1517.09 672.85,1413.45 C163.2@790.69,1413.45 C163.2@794.63,1413.45 ; pad.0@569.21,2101.81 582.27,2114.87 705.85,2238.45 C162.2@900.69,2238.45 C162.2@904.63,2238.45 ; 618.68,1888.45 668.68,1838.45 ; 623.68,1793.45 668.68,1838.45 ; C164.2@1023.49,1838.45 U15.3@768.68,1838.45 668.68,1838.45 ; C164.2@1023.97,1834.38 1023.97,1982.63 1049.21,2007.87 C161.2@1049.21,2034.68 C161.2@1049.21,2040.79 ; C167.2@1587.74,3918.45 1587.74,4002.51 1603.68,4018.45 1608.68,4023.45 1618.68,4033.45 v2(1623.68,4038.45) 1628.68,4033.45 1638.68,4023.45 1643.68,4018.45 1704.63,3957.51 1704.63,3933.45 C165.2@1704.63,3918.45 ; 1623.68,4268.45 U16.3@1623.68,4423.45 ; 1733.68,1893.45 1788.68,1838.45 U14.3@1888.68,1838.45 2058.68,1838.45 ; 1738.68,1783.45 1793.68,1838.45 ; 1743.68,2168.45 1813.68,2238.45 C158.2@1998.03,2238.45 ; C160.2@2098.68,1798.45 2058.68,1838.45 ; C160.2@2118.68,1838.45 2058.68,1838.45 ; 2118.68,1863.45 2123.68,1858.45 ; C160.2@2123.96,1794.36 2123.68,1794.67 2123.68,1960.48 2149.79,1986.59 C157.2@2167.1,1986.6 ; C159.2@2377.74,1353.45 C159.2@2381.67,1353.45 v2(2458.68,1353.45) v2(2488.68,1353.45) v2(2518.68,1353.45) v2(2548.68,1353.45) v2@2573.68,1353.45 ; C146.1@4520.08,1074.45 C146.1@4522.05,1074.45 4613.68,1074.45 4619.68,1074.45 ; NT1.2@4830.8,1051.22 v2(4906.45,1051.22) ; v4@5905.51,4528.27 J15.5@5905.51,4738.98
  Bottom Layer w78.74: C3.2@2094.41,4176.89 2094.41,4409.45 2094.41,4602.44
  Bottom Layer w100: v2@1623.68,4041.78 1623.68,4053.45 v2(1623.68,4068.45) 1623.68,4083.45 v2(1623.68,4098.45) 1623.68,4178.18 1623.68,4268.45 ; 3098.97,2103.16 3133.68,2103.16 C137.2@3224.59,2103.18
  Bottom Layer w150: J1.3@9892.52,6078.74 10010.63,6196.85 J1.2@10089.37,6196.85 10198.68,6196.85 10238.68,6196.85 10278.68,6196.85 10318.68,6196.85 10358.68,6196.85 10398.68,6196.85 10438.68,6196.85 10478.68,6196.85 10542.91,6196.85 J3.2@10739.76,6196.85 J3.2@10752.08,6196.85 ; J3.3@10542.91,6078.74 10542.91,6143.45 10542.91,6196.08
  other v1: 677.17,102.36 10031,113 10555,113 3488.19,129.92 8468.5,129.92 9086.61,129.92 6354.33,133.86 7318.9,133.86 4448.82,141.73 5228.35,141.73 5881.89,141.73 9590.55,141.73 4007.87,145.67 6846.46,145.67 7866.14,145.67 2877.95,149.61 10031,159.54 10555,159.54 10031,202 10555,202 165.35,354.33 11586.61,492.13 2720.47,622.05 6377.95,716.54 6086.61,724.41 6898,755 3748.03,771.65 6437.01,992.13 11633.86,1023.62 1602.36,1078.74 1102.36,1086.61 2570.87,1090.55 2929.13,1094.49 5237,1100 2102.36,1102.36 6122.05,1102.36 6433.07,1125.98 3559.06,1137.8 3870.08,1145.67 6127.1,1237.6 157.48,1287.4 6216.54,1330.71 2708.66,1362.2 3389.76,1370.08 5311.02,1417.32 8488.19,1535.43 11700.79,1559.06 3381.89,1669.29 5988.19,1783.46 4244.09,1972.44 4484.25,1976.38 5988.19,2027.56 11708.66,2181.1 9244.09,2212.6 10889,2222 393.7,2299.21 736.22,2429.13 169.29,2448.82 9248.03,2460.63 6665.35,2598.43 7562.99,2610.24 11704.72,2625.98 417.32,2728.35 8606.3,2732.28 10704.72,2763.78 4590.55,2771.65 7094.49,2803.15 6507.87,2814.96 8868.5,2902.4 6830.71,2937.01 11551.18,2960.63 7271.65,2972.44 9445,3070 6015.75,3185.04 3582.68,3188.98 3791.34,3188.98 1162,3221 11708.66,3291.34 2380,3322 1575,3382 6444.88,3413.39 10767.72,3488.19 2127,3498 6169.29,3543.31 5366.14,3633.86 5836,3645 6283.46,3688.98 5657.48,3700.79 8267.72,3775.59 1393.7,3779.53 8645.67,3807.09 11712.6,3811.02 9444.5,3819 11000,3870.08 7784,3873 153.54,3874.02 3864,3904 8764.4,3908.6 3516,3912 9451.7,3932 2051.18,3972.44 11157.48,3984.25 3125.98,3992.13 3259.84,3992.13 1283.46,4090.55 1732.28,4090.55 1527.56,4094.49 9023.62,4218.11 4827.1,4224.3 5960.63,4240.16 8391,4242 5377.95,4244.09 6594.49,4244.09 11586.61,4251.97 9468.9,4288.3 125.98,4346.46 4681,4371 7372,4541 3103,4605 6251.97,4669.29 11598.43,4688.98 10807.09,4704.72 759.84,4799.21 6295.28,4960.63 9124,5139 9239,5140 6221,5153 129.92,5181.1 10559.06,5322.83 7665.35,5417.32 6226.3,5487.2 5110.24,5515.75 8248.03,5618.11 129.92,5807.09 8437.01,5909.45 5046.11,5913.39 11629.92,6019.69 5446.33,6032 5500.86,6032 5555.39,6032 5609.92,6032 5664.44,6032 5718.97,6032 5773.5,6032 5827.01,6032 6817.55,6032.98 6872.08,6032.98 6926.6,6032.98 6981.13,6032.98 7035.66,6032.98 7090.19,6032.98 7144.71,6032.98 7198.23,6032.98 10909.45,6342.52 11267.72,6370.08 10035.43,6374.02 9622.05,6389.76 10472.44,6389.76 9263.78,6393.7 1877.41,6394.92 7921.26,6397.64 8933.07,6397.64 704.72,6405.51 8594.49,6405.51 1141.73,6409.45 1641.73,6409.45 8255.91,6409.45
  other v2: 2578.68,1353.45 8958.4,2928.7 9003.94,2929.13 6128.68,3083.45 1623.68,4008.45 1598.68,4023.45 1648.68,4023.45 1598.68,4053.45 1648.68,4053.45 1598.68,4083.45 1648.68,4083.45 5113.68,4223.45 7925.19,4948.97 7972.44,4948.97 8019.68,4948.97 8066.93,4948.97 8114.17,4948.97 7925.19,4996.21 7972.44,4996.21 8019.68,4996.21 8066.93,4996.21 8114.17,4996.21 7925.19,5043.45 7972.44,5043.45 8019.68,5043.45 8066.93,5043.45 8114.17,5043.45 7925.19,5090.7 7972.44,5090.7 8019.68,5090.7 8066.93,5090.7 8114.17,5090.7 9658,5115.38 9693,5115.38 9728,5115.38 7925.19,5137.94 7972.44,5137.94 8019.68,5137.94 8066.93,5137.94 8114.17,5137.94 9658,5150.38 9693,5150.38 9728,5150.38 7853.68,6243.45
  other v4: 4613.68,1058.45 4653.68,1058.45 4613.68,1113.45 4653.68,1113.45 3688.68,1303.45 3858.68,1508.45 3893.68,1508.45 3953.68,1508.45 3988.68,1508.45 3893.68,1548.45 3988.68,1548.45
  other v5: 9944.88,3326.77 10031.5,3326.77 9945.68,3366.45 10031.5,3366.14 9870.08,3401.58 9909.45,3401.58 10066.93,3401.58 10106.69,3401.58 9870.08,3488.19 9909.45,3488.19 10106.3,3488.19 9944.88,3523.62 10031.5,3523.62 9944.88,3562.99 10031.5,3562.99
  other v6: 5956.69,6252.8
  other v7: 10198.68,6143.45 10238.68,6143.45 10278.68,6143.45 10318.68,6143.45 10358.68,6143.45 10398.68,6143.45 10438.68,6143.45 10478.68,6143.45 10198.68,6248.45 10238.68,6248.45 10278.68,6248.45 10318.68,6248.45 10358.68,6248.45 10398.68,6248.45 10438.68,6248.45 10478.68,6248.45
  other v11: 8275.59,295.28 3088.68,2078.45 3133.68,2078.45 3088.68,2123.45 3133.68,2123.45
HJTAG#.HARD.TCK: HDR3.3 R287.2 | length 193.3
  Bottom Layer w5: HDR3.3@477.95,4281.1 538.58,4220.47 R287.2@646.14,4220.47
HJTAG#.HARD.TDI: HDR3.1 R284.2 | length 183.2
  Bottom Layer w5: HDR3.1@477.95,4381.1 539.02,4381.1 575.24,4417.32 R284.2@646.14,4417.32
HJTAG#.HARD.TDO: HDR3.2 R285.2 | length 324
  Bottom Layer w5: HDR3.2@377.95,4381.1 512.6,4515.75 R285.2@646.14,4515.75
HJTAG#.HARD.TMS: HDR3.4 R286.2 | length 293.6
  Bottom Layer w5: HDR3.4@377.95,4281.1 427.56,4330.71 547.24,4330.71 559.06,4318.9 R286.2@646.14,4318.9
HJTAG#.SOFT.TCK: HDR3.7 R295.2 | length 274.1
  Bottom Layer w5: HDR3.7@477.95,4081.1 542.54,4016.52 542.54,3945.91 563.25,3925.2 R295.2@646.14,3925.2
HJTAG#.SOFT.TDI: HDR3.5 R292.2 | length 192.6
  Bottom Layer w5: HDR3.5@477.95,4181.1 538.23,4181.1 597.28,4122.05 R292.2@646.14,4122.05
HJTAG#.SOFT.TDO: HDR3.6 R293.2 | length 351.2
  Bottom Layer w5: HDR3.6@377.95,4181.1 429.13,4129.92 510.23,4129.92 533.54,4106.61 533.54,4076.26 586.18,4023.62 R293.2@646.14,4023.62
HJTAG#.SOFT.TMS: HDR3.8 R294.2 | length 446.4
  Bottom Layer w5: HDR3.8@377.95,4081.1 427,4032.06 427,3907.65 507.88,3826.77 R294.2@646.14,3826.77
HJTAG.HARD.TCK: R283.1 R287.1 U5.B24 U7.H3 | length 11565.3
  Top Layer w5: U5.B24@10401.58,3897.64 10421.26,3917.32 10421.26,3952.76 10456.69,3988.19 10549.19,3988.19 v1(10617,4056) ; v1(10783.46,4350.39) 10874.02,4259.84 10929.13,4259.84 10960.63,4291.34 11110.24,4291.34 U7.H3@11125.98,4275.59
  MidLayer4 w5: v1(755.91,4220.47) 781.7,4220.47 821.68,4260.45 960.68,4260.45 979.76,4279.53 3477.68,4279.53 3513.11,4314.96 3888.46,4314.96 4038.07,4165.36 9299.44,4165.36 9433.3,4299.21 9446.54,4312.45 9918.68,4312.45 10110.68,4504.45 10467.15,4504.45 10582.68,4388.93 ; v1(10617,4056) 10531.5,4141.5 10531.5,4299.21 10582.68,4350.39 10582.68,4388.93 ; v1(10783.46,4350.39) 10736.86,4397 10590.75,4397 10582.68,4388.93
  Bottom Layer w11.81: R287.1@688.5,4220.47 R283.1@823.31,4220.47
HJTAG.HARD.TDI: R280.1 R284.1 U5.C1 | length 10502.4
  Top Layer w5: v1(9446.9,4263.8) 9444.88,4365.58 9430.7,4379.76 9147.46,4379.76 9140,4372.3 9140,3889.24 9159.24,3870 9286.14,3870 9303.62,3852.52 9470.63,3852.52 9476.38,3858.27 U5.C1@9496.06,3858.27
  MidLayer4 w5: v1(755.91,4417.32) 755.91,4366.14 732.28,4342.52 732.28,4204.73 744.09,4192.91 772.56,4192.91 824.1,4244.45 964.68,4244.45 987.94,4267.72 3482.57,4267.72 3518.01,4303.15 3883.57,4303.15 4033.17,4153.54 9304.34,4153.54 9391.87,4241.07 9414.59,4263.8 v1(9446.9,4263.8)
  Bottom Layer w11.81: R284.1@688.5,4417.32 R280.1@823.31,4417.32
HJTAG.HARD.TDO: R281.1 R285.1 U7.E6 | length 11127.2
  Top Layer w5: v1(10657.48,4452.76) 10657.48,4421.26 10673.23,4405.51 10791.34,4405.51 10870.08,4326.77 10992.13,4326.77 11019.69,4354.33 11204.72,4354.33 U7.E6@11220.47,4370.08
  MidLayer4 w5: v1(755.91,4515.75) 783.46,4488.19 783.46,4326.77 820.78,4289.45 954.68,4289.45 968.38,4303.15 3467.9,4303.15 3503.33,4338.58 3898.25,4338.58 4047.85,4188.98 9289.66,4188.98 9448.14,4347.45 9904.68,4347.45 10081.68,4524.45 10585.78,4524.45 v1(10657.48,4452.76)
  Bottom Layer w11.81: R285.1@688.5,4515.75 v1(755.91,4515.75) R281.1@823.31,4515.75
HJTAG.HARD.TMS: R282.1 R286.1 U5.A24 U7.E2 | length 11501.6
  Top Layer w5: U5.A24@10401.58,3937.01 10401.58,3956.69 10429.13,3984.25 v1(10429.13,4156.5) ; v1(10688.98,4433.07) 10799.21,4433.07 10846.46,4385.83 11078.74,4385.83 U7.E2@11094.49,4370.08
  MidLayer1 w5: v1(10429.13,4156.5) 10429.13,4341.83 10520.37,4433.07 v1(10688.98,4433.07)
  MidLayer4 w5: v1(755.91,4318.9) 800.64,4274.16 954.39,4274.16 971.57,4291.34 3472.79,4291.34 3508.22,4326.77 3893.35,4326.77 4042.96,4177.17 9294.55,4177.17 9439.84,4322.45 9905.68,4322.45 10097.68,4514.45 10549.74,4514.45 10646.28,4417.92 10673.82,4417.92 v1(10688.98,4433.07)
  Bottom Layer w11.81: R286.1@688.5,4318.9 v1(755.91,4318.9) R282.1@823.31,4318.9
HJTAG.SOFT.TCK: R291.1 R295.1 U5.H13 | length 10227.2
  Top Layer w7.87: v5@9948.82,3681.1 U5.H13@9968.5,3661.42
  MidLayer4 w5: v1(755.91,3925.2) 781.3,3925.2 838.66,3982.55 931.37,3982.55 982.29,4033.47 982.29,4202.07 1012.51,4232.28 3497.25,4232.28 3532.68,4267.72 3868.89,4267.72 4018.5,4118.11 9319.01,4118.11 9421.36,4220.45 9899.27,4220.45 9939.14,4180.59 9939.14,4123.86 9939.13,3902.37 9968.5,3873 9968.5,3700.79 v5@9948.82,3681.1
  Bottom Layer w11.81: R295.1@688.5,3925.2 v1(755.91,3925.2) R291.1@823.31,3925.2
  other v5: 9944.88,3681.1
HJTAG.SOFT.TDI: R288.1 R292.1 U5.F14 | length 10056.5
  Top Layer w7.87: U5.F14@10007.87,3740.16 v1(10027.56,3759.84)
  MidLayer4 w5: v1(755.91,4122.05) 863.28,4122.05 997.13,4255.91 3487.47,4255.91 3522.9,4291.34 3878.68,4291.34 4028.28,4141.73 9309.23,4141.73 9411.95,4244.45 9909.09,4244.45 9959.13,4194.41 9959.13,3910.65 10011.79,3858 10039.24,3858 10047.24,3850 10047.24,3779.53 v1(10027.56,3759.84)
  Bottom Layer w11.81: R292.1@688.5,4122.05 v1(755.91,4122.05) R288.1@823.31,4122.05
HJTAG.SOFT.TDO: R289.1 R293.1 U5.H14 | length 10157.9
  Top Layer w7.87: U5.H14@10007.87,3661.42 v5@10027.56,3681.1
  MidLayer4 w5: v1(755.91,4023.62) 785.24,4023.62 852.92,4091.3 911.47,4091.3 947.18,4127 947.18,4185.17 1006.1,4244.1 3492.36,4244.1 3527.79,4279.53 3873.78,4279.53 4023.39,4129.92 9314.12,4129.92 9418.65,4234.45 9899.41,4234.45 9949.13,4184.73 9949.13,3906.51 10007.87,3847.77 10007.87,3700.79 v5@10027.56,3681.1
  Bottom Layer w11.81: R293.1@688.5,4023.62 v1(755.91,4023.62) R289.1@823.31,4023.62
  other v5: 10031.5,3681.1
HJTAG.SOFT.TMS: R290.1 R294.1 U5.F13 | length 10164.9
  Top Layer w7.87: v1(9948.82,3759.84) U5.F13@9968.5,3740.16
  MidLayer4 w5: v1(755.91,3826.77) 831.98,3826.77 994.68,3989.48 994.68,4196 1019.16,4220.47 3502.14,4220.47 3537.58,4255.91 3864,4255.91 4013.61,4106.3 9323.91,4106.3 9423.06,4205.45 9900.13,4205.45 9929.13,4176.44 9929.13,4019.69 9929.13,4000 9929.13,3779.53 v1(9948.82,3759.84)
  Bottom Layer w11.81: R294.1@688.5,3826.77 v1(755.91,3826.77) R290.1@813.78,3826.77
HOST_DIN: U5.Y15 U7.H6 | length 3782.4
  Top Layer w5: v1(10787.4,4200.79) 10831.49,4156.7 11129.14,4156.7 11220.47,4248.03 U7.H6@11220.47,4275.59
  Top Layer w7.87: U5.Y15@10047.24,3188.98 v1(10066.93,3169.29)
  MidLayer4 w5: v1(10011,2588) 10055,2632 v1(10055,2732)
  MidLayer3 w5: v1(10011,2588) 9908,2588 9905,2591 9905,2637 9912,2644 10092,2644 10119,2671 10530.87,2671 10571.86,2711.99 10571.86,2786.86 10635,2850 10635,2950 10645,2960 10772.4,2960 10787.4,2975 v1(10787.4,4200.79) ; v1(10055,2732) 10109.29,2732 10184.82,2807.53 10184.82,2878.18 10086.74,2976.26 10086.74,3149.48 v1(10066.93,3169.29)
HOST_INIT: R52.2 U5.AC14 U7.A3 | length 3810.6
  Top Layer w5: v1(10933.07,4527.56) 10964.57,4527.56 10976.38,4539.37 11110.24,4539.37 11125.98,4523.62 U7.A3@11125.98,4496.06
  Top Layer w7.87: U5.AC14@10007.87,3070.87 v1(10027.56,3051.18)
  MidLayer1 w5: v1(9942,2620) 10011,2689 10011,2749.55 10015.75,2754.3 10015.75,2992.13 10007.87,3000 10007.87,3031.49 v1(10027.56,3051.18)
  MidLayer2 w5: v1(10680,4376) 10913,4376 10933.07,4396.07 v1(10933.07,4527.56)
  MidLayer3 w5: v1(9942,2620) 10093,2620 10134,2661 10535.02,2661 10622.05,2748.03 10822.83,2948.82 10822.83,4098.43 10850.39,4125.98 10857,4132.59 10857,4305.82 10933.07,4381.89 v1(10933.07,4527.56)
  Bottom Layer w5: R52.2@10641.64,4388.25 10667.75,4388.25 v1(10680,4376)
HOST_LED.L0: LED1.1 U5.Y6 | length 7289.9
  Top Layer w5: v2(5086.22,1972.44) LED1.1@5137.8,1972.44
  Top Layer w7.87: v1(9673.23,3169.29) U5.Y6@9692.91,3188.98
  MidLayer2 w5: v2(5086.22,1972.44) 4942.73,1828.95 4942.73,1182 4976.37,1148.36 5405.53,1148.36 5484.87,1227.7 6053.02,1227.7 6122.05,1296.73 v2(6122.05,1330.71)
  MidLayer4 w5: v2(6122.05,1330.71) 6157.48,1366.14 6157.48,1405.51 6145.89,1417.1 6145.89,1459.87 6323.82,1637.8 7543.31,1637.8 7858.27,1952.76 7858.27,2948.82 7929.13,3019.69 8191.49,3019.69 8447.4,3275.59 9235.24,3275.59 9361.23,3149.61 9413.39,3149.61 9433.07,3149.61 9653.54,3149.61 v1(9673.23,3169.29)
HOST_LED.L1: LED2.1 U5.W6 | length 7153.8
  Top Layer w5: v2(5086.22,1874.02) LED2.1@5137.8,1874.02
  Top Layer w7.87: v1(9673.23,3208.66) U5.W6@9692.91,3228.35
  MidLayer2 w5: v2(5086.22,1874.02) 4956.52,1744.32 4956.52,1209.97 5008.13,1158.36 5399.87,1158.36 5481.43,1239.92 6036.08,1239.92 6094.49,1298.33 v2(6094.49,1358.27)
  MidLayer4 w5: v2(6094.49,1358.27) 6129.92,1358.27 6145.67,1374.02 6145.67,1401.58 6133.86,1413.39 6133.86,1463.58 6319.88,1649.61 7539.37,1649.61 7846.46,1956.69 7846.46,2952.76 7925.2,3031.5 8186.6,3031.5 8442.51,3287.4 9237.58,3287.4 9336,3188.98 9413.39,3188.98 9433.07,3188.98 9653.54,3188.98 v1(9673.23,3208.66)
HOST_LED.L2: LED3.1 U5.V6 | length 6995.1
  Top Layer w5: v2(5086.22,1775.59) LED3.1@5137.8,1775.59
  Top Layer w7.87: v1(9673.23,3248.03) U5.V6@9692.91,3267.72
  MidLayer2 w5: v2(5086.22,1775.59) 4970.31,1659.68 4970.31,1218.25 5016.41,1172.15 5393.38,1172.15 5477.69,1256.47 6022.29,1256.47 6070.68,1304.86 6070.68,1370.45 6086.06,1385.83 v2(6122.05,1385.83)
  MidLayer4 w5: v2(6122.05,1385.83) 6122.05,1467.52 6315.95,1661.42 7535.43,1661.42 7834.65,1960.63 7834.65,2956.69 7921.26,3043.31 8181.71,3043.31 8437.62,3299.21 9239.91,3299.21 9310.77,3228.35 9413.39,3228.35 9433.07,3228.35 9653.54,3228.35 v1(9673.23,3248.03)
HOST_LED.L3: LED4.1 U5.U6 | length 6832.3
  Top Layer w5: v2(5086.22,1677.17) LED4.1@5137.8,1677.17
  Top Layer w7.87: v1(9673.23,3287.4) U5.U6@9692.91,3307.09
  MidLayer2 w5: v2(5086.22,1677.17) 4991.19,1582.14 4991.19,1228.89 5032.56,1187.52 5388.74,1187.52 5504.97,1303.75 6040.41,1303.75 6054.2,1317.54 6054.2,1373.1 v2(6094.49,1413.39)
  MidLayer4 w5: v2(6094.49,1413.39) 6094.49,1455.71 6312.01,1673.23 7531.5,1673.23 7822.83,1964.57 7822.83,2960.63 7917.32,3055.12 8176.82,3055.12 8432.72,3311.02 9242.24,3311.02 9309.17,3244.1 9413.39,3244.1 9433.07,3244.1 9519.69,3244.1 9543.31,3267.72 9653.54,3267.72 v1(9673.23,3287.4)
HOST_LED.L4: LED5.1 U5.T6 | length 6726.3
  Top Layer w5: v2(5086.22,1578.74) LED5.1@5137.8,1578.74 ; v2@5098.43,1578.74 LED5.1@5133.86,1578.74
  Top Layer w7.87: v1(9673.23,3326.77) U5.T6@9692.91,3346.46
  MidLayer2 w5: v2(5086.22,1578.74) 5013.26,1505.78 5013.26,1245.43 5058.57,1200.12 5382.35,1200.12 5512.94,1330.71 v2(6031.5,1330.71)
  MidLayer4 w5: v2(6031.5,1330.71) 6066.93,1366.14 6066.93,1409.45 6062.99,1413.39 6062.99,1439.96 6308.07,1685.04 7527.56,1685.04 7811.02,1968.5 7811.02,2964.57 7913.39,3066.93 8171.93,3066.93 8427.83,3322.84 9244.57,3322.84 9300.4,3267 9381.17,3267 9433.07,3318.9 9492.13,3318.9 9503.94,3307.09 9653.54,3307.09 v1(9673.23,3326.77)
